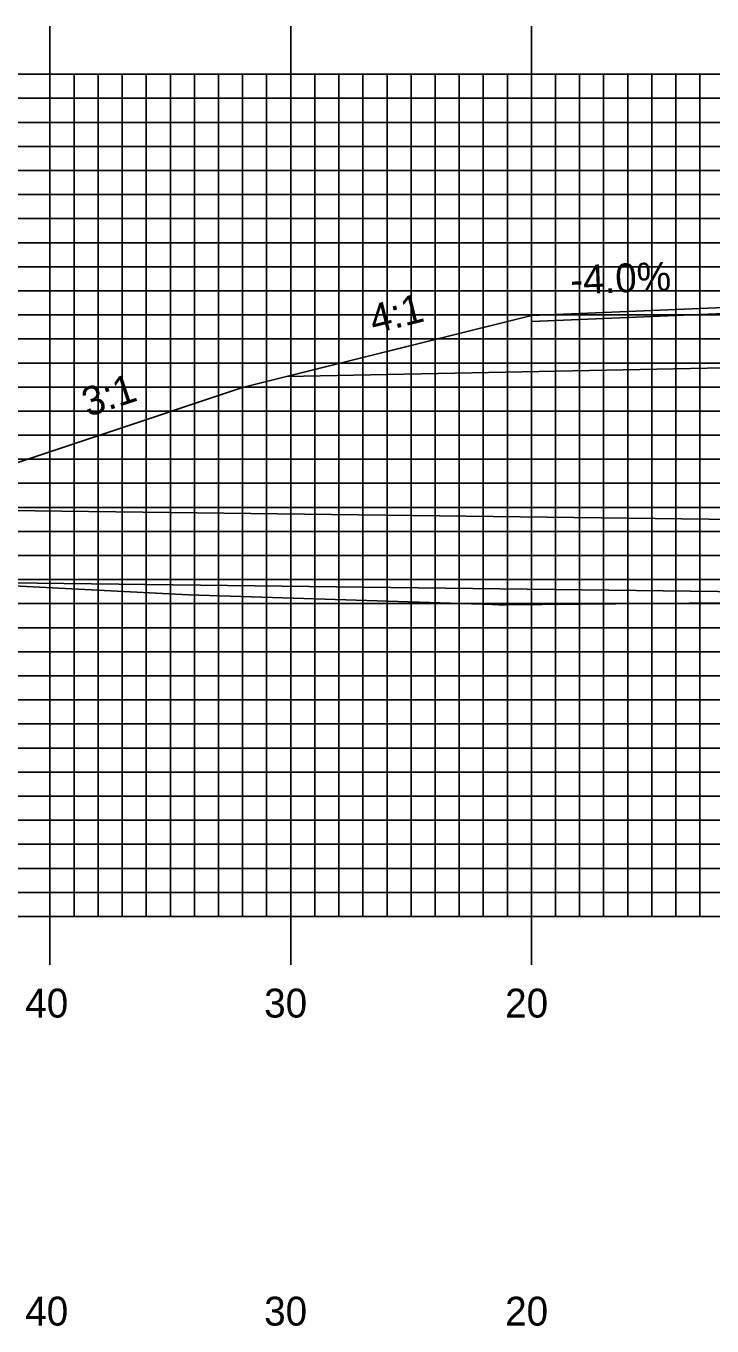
# Model space of a CAD drawing. Extents: x 1807045 to 1807388, y 442591 to 442811.
# Drawn here: x 1807169.8 to 1807198.3, y 442646.6 to 442700.7 of the extents above; entities that cross this region are included whole.
import ezdxf

# ---------------------------------------------------------------- set-up
doc = ezdxf.new("R2010")
doc.units = 0
for name, color, linetype in [('ANNOTATION', 7, 'Continuous'), ('D_Drainage_Culvert', 7, 'Continuous'), ('D_Roadway_Centerline', 7, 'Continuous'), ('D_Roadway_Edge_Shoulder', 7, 'Continuous'), ('D_Roadway_SlopeLines', 7, 'Continuous'), ('D_Roadway_SubGrade', 7, 'Continuous'), ('H_V ANNOTATION', 7, 'Continuous'), ('MAJOR', 7, 'Continuous'), ('MINOR', 7, 'Continuous'), ('S_Roadway_Centerline', 7, 'Continuous')]:
    doc.layers.add(name, color=color, linetype=linetype)

msp = doc.modelspace()

# ---------------------------------------------------------------- linework, layer by layer
at = {"layer": 'D_Drainage_Culvert'}
msp.add_lwpolyline([(1807157.759, 442677.672), (1807269.759, 442676.294), (1807269.796, 442679.294), (1807157.804, 442680.672)], close=True, dxfattribs=at)
at = {"layer": 'D_Roadway_Centerline'}
msp.add_lwpolyline([(1807166.273, 442681.484), (1807178.759, 442685.646), (1807180.585, 442686.103), (1807190.759, 442688.646), (1807198.759, 442688.966), (1807210.759, 442689.206), (1807222.759, 442688.966), (1807230.759, 442688.646), (1807240.933, 442686.103), (1807242.759, 442685.646), (1807258.793, 442680.302)], dxfattribs=at)
at = {"layer": 'D_Roadway_Edge_Shoulder'}
msp.add_lwpolyline([(1807198.759, 442688.966), (1807190.759, 442688.646), (1807190.759, 442688.396), (1807198.759, 442688.716)], close=True, dxfattribs=at)
at = {"layer": 'D_Roadway_SlopeLines'}
msp.add_lwpolyline([(1807190.759, 442688.646), (1807178.759, 442685.646), (1807166.273, 442681.484)], dxfattribs=at)
at = {"layer": 'D_Roadway_SubGrade'}
msp.add_lwpolyline([(1807198.759, 442686.466), (1807180.585, 442686.103), (1807190.759, 442688.646), (1807190.759, 442688.396), (1807198.759, 442688.716), (1807210.759, 442688.956), (1807222.759, 442688.716), (1807230.759, 442688.396), (1807230.759, 442688.646), (1807240.933, 442686.103), (1807222.759, 442686.466), (1807210.759, 442686.706)], close=True, dxfattribs=at)
at = {"layer": 'MAJOR'}
for p, q in [((1807170.759, 442700.669), (1807170.759, 442698.665)), ((1807180.759, 442700.669), (1807180.759, 442698.665)), ((1807190.759, 442700.669), (1807190.759, 442698.665)), ((1807070.759, 442698.665), (1807350.759, 442698.665)), ((1807070.759, 442698.665), (1807350.759, 442698.665)), ((1807170.759, 442663.665), (1807170.759, 442698.665)), ((1807180.759, 442663.665), (1807180.759, 442698.665)), ((1807190.759, 442663.665), (1807190.759, 442698.665)), ((1807070.759, 442693.665), (1807350.759, 442693.665)), ((1807070.759, 442688.665), (1807350.759, 442688.665)), ((1807070.759, 442683.665), (1807350.759, 442683.665)), ((1807070.759, 442678.665), (1807350.759, 442678.665)), ((1807070.759, 442673.665), (1807350.759, 442673.665)), ((1807070.759, 442668.665), (1807350.759, 442668.665)), ((1807070.759, 442663.665), (1807350.759, 442663.665)), ((1807070.759, 442663.665), (1807350.759, 442663.665)), ((1807170.759, 442661.661), (1807170.759, 442663.665)), ((1807180.759, 442661.661), (1807180.759, 442663.665)), ((1807190.759, 442661.661), (1807190.759, 442663.665))]:
    msp.add_line(p, q, dxfattribs=at)
at = {"layer": 'MINOR'}
for p, q in [((1807171.759, 442663.665), (1807171.759, 442698.665)), ((1807172.759, 442663.665), (1807172.759, 442698.665)), ((1807173.759, 442663.665), (1807173.759, 442698.665)), ((1807174.759, 442663.665), (1807174.759, 442698.665)), ((1807175.759, 442663.665), (1807175.759, 442698.665)), ((1807176.759, 442663.665), (1807176.759, 442698.665)), ((1807177.759, 442663.665), (1807177.759, 442698.665)), ((1807178.759, 442663.665), (1807178.759, 442698.665)), ((1807179.759, 442663.665), (1807179.759, 442698.665)), ((1807181.759, 442663.665), (1807181.759, 442698.665)), ((1807182.759, 442663.665), (1807182.759, 442698.665)), ((1807183.759, 442663.665), (1807183.759, 442698.665)), ((1807184.759, 442663.665), (1807184.759, 442698.665)), ((1807185.759, 442663.665), (1807185.759, 442698.665)), ((1807186.759, 442663.665), (1807186.759, 442698.665)), ((1807187.759, 442663.665), (1807187.759, 442698.665)), ((1807188.759, 442663.665), (1807188.759, 442698.665)), ((1807189.759, 442663.665), (1807189.759, 442698.665)), ((1807191.759, 442663.665), (1807191.759, 442698.665)), ((1807192.759, 442663.665), (1807192.759, 442698.665)), ((1807193.759, 442663.665), (1807193.759, 442698.665)), ((1807194.759, 442663.665), (1807194.759, 442698.665)), ((1807195.759, 442663.665), (1807195.759, 442698.665)), ((1807196.759, 442663.665), (1807196.759, 442698.665)), ((1807197.759, 442663.665), (1807197.759, 442698.665)), ((1807070.759, 442697.665), (1807350.759, 442697.665)), ((1807070.759, 442696.665), (1807350.759, 442696.665)), ((1807070.759, 442695.665), (1807350.759, 442695.665)), ((1807070.759, 442694.665), (1807350.759, 442694.665)), ((1807070.759, 442692.665), (1807350.759, 442692.665)), ((1807070.759, 442691.665), (1807350.759, 442691.665)), ((1807070.759, 442690.665), (1807350.759, 442690.665)), ((1807070.759, 442689.665), (1807350.759, 442689.665)), ((1807070.759, 442687.665), (1807350.759, 442687.665)), ((1807070.759, 442686.665), (1807350.759, 442686.665)), ((1807070.759, 442685.665), (1807350.759, 442685.665)), ((1807070.759, 442684.665), (1807350.759, 442684.665)), ((1807070.759, 442682.665), (1807350.759, 442682.665)), ((1807070.759, 442681.665), (1807350.759, 442681.665)), ((1807070.759, 442680.665), (1807350.759, 442680.665)), ((1807070.759, 442679.665), (1807350.759, 442679.665)), ((1807070.759, 442677.665), (1807350.759, 442677.665)), ((1807070.759, 442676.665), (1807350.759, 442676.665)), ((1807070.759, 442675.665), (1807350.759, 442675.665)), ((1807070.759, 442674.665), (1807350.759, 442674.665)), ((1807070.759, 442672.665), (1807350.759, 442672.665)), ((1807070.759, 442671.665), (1807350.759, 442671.665)), ((1807070.759, 442670.665), (1807350.759, 442670.665)), ((1807070.759, 442669.665), (1807350.759, 442669.665)), ((1807070.759, 442667.665), (1807350.759, 442667.665)), ((1807070.759, 442666.665), (1807350.759, 442666.665)), ((1807070.759, 442665.665), (1807350.759, 442665.665)), ((1807070.759, 442664.665), (1807350.759, 442664.665))]:
    msp.add_line(p, q, dxfattribs=at)
at = {"layer": 'S_Roadway_Centerline'}
msp.add_lwpolyline([(1807137.321, 442678.055), (1807145.714, 442677.905), (1807153.421, 442677.695), (1807163.888, 442677.64), (1807167.09, 442677.522), (1807176.514, 442677.036), (1807189.139, 442676.626), (1807189.4, 442676.62), (1807189.676, 442676.614), (1807203.419, 442676.739), (1807210.876, 442676.624), (1807214.273, 442676.566), (1807222.824, 442676.92), (1807231.138, 442676.312), (1807247.162, 442676.483), (1807251.677, 442676.55), (1807259.938, 442676.383), (1807289.258, 442676.117)], dxfattribs=at)

# ---------------------------------------------------------------- texts
at = {"layer": 'ANNOTATION'}
for s, rotation, p in [('-4.0%', 2.2906, (1807192.391, 442689.513)), ('4:1', 14.0362, (1807184.207, 442687.87)), ('3:1', 18.4348, (1807172.336, 442684.414))]:
    msp.add_text(s, height=1.2, rotation=rotation, dxfattribs=at).set_placement(p)
at = {"layer": 'H_V ANNOTATION'}
for s, p in [('40', (1807169.731, 442659.465)), ('30', (1807179.656, 442659.465)), ('20', (1807189.667, 442659.465)), ('40', (1807169.731, 442646.665)), ('30', (1807179.656, 442646.665)), ('20', (1807189.667, 442646.665))]:
    msp.add_text(s, height=1.2, dxfattribs=at).set_placement(p)

doc.saveas('drawing.dxf')
